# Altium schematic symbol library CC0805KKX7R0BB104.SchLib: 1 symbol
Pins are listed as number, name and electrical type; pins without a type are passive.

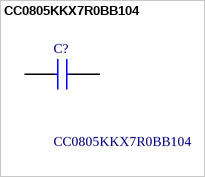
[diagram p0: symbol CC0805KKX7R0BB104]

## CC0805KKX7R0BB104
designator C?
YAGEO - CC0805KKX7R0BB104 - SMD Multilayer Ceramic Capacitor, 0.1 F, 100 V, 0805 [2012 Metric], +/- 10%, X7R, CC Series; Geometry.Height: 1.45mm
footprint CAPC2012X145N
pins: 1, 2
